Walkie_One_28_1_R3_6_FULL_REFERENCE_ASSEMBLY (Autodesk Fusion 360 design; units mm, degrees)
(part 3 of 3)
sketch "Sketch14" plane through (0, 0, -22) normal (0, 0, 1) x axis (1, 0, 0)
  line L1 (26.9755, 27.0732) -> (16.9755, 27.0732)
  line L2 (26.9755, 19.0732) -> (26.9755, 27.0732)
  line L3 (16.9755, 19.0732) -> (26.9755, 19.0732)
  line L4 (16.9755, 27.0732) -> (16.9755, 19.0732)
  line L5 (-26.4387, -62.9268) -> (-16.9755, -62.9268)
  curve K1 (-20, -67) -> (-25.5105, -65.6599)
  line L6 (20, -67) -> (-20, -67)
  curve K2 (25.5105, -65.6599) -> (20, -67)
  curve K3 (32, -55) -> (30.6599, -60.5105)
  line L7 (32, 1.6132) -> (32, -55)
  line L8 (22.6952, 1.6132) -> (32, 1.6132)
  line L9 (22.6952, 5.6132) -> (22.6952, 1.6132)
  line L10 (32, 5.6132) -> (22.6952, 5.6132)
  line L11 (32, 55) -> (32, 5.6132)
  curve K4 (30.6599, 60.5105) -> (32, 55)
  line L12 (-20, 67) -> (20, 67)
  curve K5 (-25.5105, 65.6599) -> (-20, 67)
  line L13 (-32, -55) -> (-32, 55)
  curve K6 (-30.6599, -60.5105) -> (-32, -55)
  line L14 (-26.9755, -54.9268) -> (-26.9755, -62.2512)
  line L15 (-16.9755, -54.9268) -> (-26.9755, -54.9268)
  line L16 (-16.9755, -62.9268) -> (-16.9755, -54.9268)
  curve K7 (20, 67) -> (25.5105, 65.6599)
  curve K8 (-32, 55) -> (-30.6599, 60.5105)
  arc A1 centre (-31, -66) radius 5.5 clockwise from (-26.4387, -62.9268) to (-25.5105, -65.6599)
  arc A2 centre (31, -66) radius 5.5 clockwise from (25.5105, -65.6599) to (30.6599, -60.5105)
  arc A3 centre (31, 66) radius 5.5 clockwise from (30.6599, 60.5105) to (25.5105, 65.6599)
  arc A4 centre (-31, 66) radius 5.5 clockwise from (-25.5105, 65.6599) to (-30.6599, 60.5105)
  arc A5 centre (-31, -66) radius 5.5 clockwise from (-30.6599, -60.5105) to (-26.9755, -62.2512)
  circle C1 centre (-26, 28) radius 3.5
  circle C2 centre (26, 56) radius 3.5
  circle C3 centre (-25, 56) radius 3.5
  dimension "d391" diameter C1 = 7
  dimension "d392" diameter C2 = 7
  dimension "d393" diameter C3 = 7
extrude "Extrude15" add sketch "Sketch14" profile of C1 C2 C3 along normal blind 5.35
fillet "Fillet4" radius 1
position "Position10"
copy_paste "CutPaste"
sketch "Sketch23" plane through (0, 0, 0) normal (0, 0, 1) x axis (1, 0, 0)
  line L1 (32, 55) -> (32, -55)
  line L2 (-20, 67) -> (20, 67)
  line L3 (-32, -55) -> (-32, 55)
  line L4 (20, -67) -> (-20, -67)
  line L5 (-12.5, 62.5) -> (12.5, 62.5)
  line L6 (-24, 24) -> (-24, 51)
  line L7 (12.5, 12.5) -> (-12.5, 12.5)
  line L8 (24, 51) -> (24, 24)
  line L9 (12.5, 60.5) -> (-12.5, 60.5)
  line L10 (-22, 51) -> (-22, 24)
  line L11 (22, 24) -> (22, 51)
  line L12 (-12.5, 14.5) -> (12.5, 14.5)
  arc A1 centre (20, -55) radius 12 clockwise from (32, -55) to (20, -67)
  arc A2 centre (20, 55) radius 12 clockwise from (20, 67) to (32, 55)
  arc A3 centre (-20, 55) radius 12 clockwise from (-32, 55) to (-20, 67)
  arc A4 centre (-20, -55) radius 12 clockwise from (-20, -67) to (-32, -55)
  circle C1 centre (-0.0141, 38) radius 18
  circle C2 centre (0, 0) radius 2.4048
  circle C3 centre (0.0002, -18.0006) radius 1.3009
  circle C4 centre (0, -47) radius 15.55
  arc A5 centre (-12.5, 51) radius 11.5 clockwise from (-24, 51) to (-12.5, 62.5)
  arc A6 centre (-12.5, 24) radius 11.5 clockwise from (-12.5, 12.5) to (-24, 24)
  arc A7 centre (12.5, 24) radius 11.5 clockwise from (24, 24) to (12.5, 12.5)
  arc A8 centre (12.5, 51) radius 11.5 clockwise from (12.5, 62.5) to (24, 51)
  arc A9 centre (-12.5, 51) radius 9.5 clockwise from (-22, 51) to (-12.5, 60.5)
  arc A10 centre (12.5, 51) radius 9.5 clockwise from (12.5, 60.5) to (22, 51)
  arc A11 centre (12.5, 24) radius 9.5 clockwise from (22, 24) to (12.5, 14.5)
  arc A12 centre (-12.5, 24) radius 9.5 clockwise from (-12.5, 14.5) to (-22, 24)
extrude "Extrude23" new body of existing geometry blind -1 from offset -0.6
sketch "Sketch24" plane through (0, 0, 0.95) normal (0, 0, 1) x axis (1, 0, 0)
  line L1 (-22, 51) -> (-22, 24)
  line L2 (12.5, 60.5) -> (-12.5, 60.5)
  line L3 (22, 24) -> (22, 51)
  line L4 (-12.5, 14.5) -> (12.5, 14.5)
  line L5 (-12.5, 62.5) -> (12.5, 62.5)
  line L6 (-24, 24) -> (-24, 51)
  line L7 (12.5, 12.5) -> (-12.5, 12.5)
  line L8 (24, 51) -> (24, 24)
  arc A1 centre (-12.5, 24) radius 9.5 clockwise from (-12.5, 14.5) to (-22, 24)
  arc A2 centre (-12.5, 51) radius 9.5 clockwise from (-22, 51) to (-12.5, 60.5)
  arc A3 centre (12.5, 51) radius 9.5 clockwise from (12.5, 60.5) to (22, 51)
  arc A4 centre (12.5, 24) radius 9.5 clockwise from (22, 24) to (12.5, 14.5)
  arc A5 centre (-12.5, 51) radius 11.5 clockwise from (-24, 51) to (-12.5, 62.5)
  arc A6 centre (-12.5, 24) radius 11.5 clockwise from (-12.5, 12.5) to (-24, 24)
  arc A7 centre (12.5, 24) radius 11.5 clockwise from (24, 24) to (12.5, 12.5)
  arc A8 centre (12.5, 51) radius 11.5 clockwise from (12.5, 62.5) to (24, 51)
sketch "Sketch14" plane through (0, 0, 0.95) normal (0, 0, 1) x axis (1, 0, 0)
  line L1 (-22, 51) -> (-22, 24)
  line L2 (12.5, 60.5) -> (-12.5, 60.5)
  line L3 (22, 24) -> (22, 51)
  line L4 (-12.5, 14.5) -> (12.5, 14.5)
  line L5 (-12.5, 62.5) -> (12.5, 62.5)
  line L6 (-24, 24) -> (-24, 51)
  line L7 (12.5, 12.5) -> (-12.5, 12.5)
  line L8 (24, 51) -> (24, 24)
  line L9 (12.5, 12.5) -> (-12.5, 12.5)
  line L10 (-24, 24) -> (-24, 51)
  line L11 (-12.5, 62.5) -> (12.5, 62.5)
  line L12 (24, 51) -> (24, 24)
  line L13 (-21, 24) -> (-21, 51)
  line L14 (12.5, 15.5) -> (-12.5, 15.5)
  line L15 (21, 51) -> (21, 24)
  line L16 (-12.5, 59.5) -> (12.5, 59.5)
  arc A1 centre (-12.5, 24) radius 9.5 clockwise from (-12.5, 14.5) to (-22, 24)
  arc A2 centre (-12.5, 51) radius 9.5 clockwise from (-22, 51) to (-12.5, 60.5)
  arc A3 centre (12.5, 51) radius 9.5 clockwise from (12.5, 60.5) to (22, 51)
  arc A4 centre (12.5, 24) radius 9.5 clockwise from (22, 24) to (12.5, 14.5)
  arc A5 centre (-12.5, 51) radius 11.5 clockwise from (-24, 51) to (-12.5, 62.5)
  arc A6 centre (-12.5, 24) radius 11.5 clockwise from (-12.5, 12.5) to (-24, 24)
  arc A7 centre (12.5, 24) radius 11.5 clockwise from (24, 24) to (12.5, 12.5)
  arc A8 centre (12.5, 51) radius 11.5 clockwise from (12.5, 62.5) to (24, 51)
  arc A9 centre (12.5, 24) radius 11.5 clockwise from (24, 24) to (12.5, 12.5)
  arc A10 centre (-12.5, 24) radius 11.5 clockwise from (-12.5, 12.5) to (-24, 24)
  arc A11 centre (-12.5, 51) radius 11.5 clockwise from (-24, 51) to (-12.5, 62.5)
  arc A12 centre (12.5, 51) radius 11.5 clockwise from (12.5, 62.5) to (24, 51)
  arc A13 centre (-12.5, 24) radius 8.5 clockwise from (-12.5, 15.5) to (-21, 24)
  arc A14 centre (12.5, 24) radius 8.5 clockwise from (21, 24) to (12.5, 15.5)
  arc A15 centre (12.5, 51) radius 8.5 clockwise from (12.5, 59.5) to (21, 51)
  arc A16 centre (-12.5, 51) radius 8.5 clockwise from (-21, 51) to (-12.5, 59.5)
  dimension "d402" = -3
place_component sketch "Sketch14"
extrude "Extrude1" new body sketch "Sketch14" along normal blind 2
delete_face "DeleteFace2"
delete_face "DeleteFace3"
sketch "Sketch15" plane through (-40, 0, 0) normal (-1, 0, 0) x axis (0, 0, 1)
  line L1 (-13.1579, -20.1868) -> (-12, -20.1868)
  line L2 (-16, -19.497) -> (-16, -55)
  line L3 (-12, -55) -> (-16, -55)
  line L4 (-12, -20.1868) -> (-12, -55)
  line L5 (-16.6, -42.5) -> (-15.5, -49.6)
  line L6 (-10.55, -37.05) -> (-21.55, -37.05)
  line L7 (-10.55, -55.05) -> (-10.55, -37.05)
  line L8 (-21.55, -55.05) -> (-10.55, -55.05)
  line L9 (-21.55, -37.05) -> (-21.55, -55.05)
  line L10 (-10.55, -55.05) -> (-21.55, -37.05)
  line L11 (-21.55, -55.05) -> (-10.55, -37.05)
  arc A1 centre (-13.1579, -13.9868) radius 6.2 clockwise from (-13.1579, -20.1868) to (-16, -19.497)
  point P14 (-16.05, -46.05)
  point P12 (-10.55, -55.05)
  point P13 (-21.55, -55.05)
  point P11 (-10.55, -37.05)
  horizontal L6
  perpendicular L6 L7
  parallel L6 L8
  parallel L7 L9
  coincident L10 P14
  coincident L11 P14
  midpoint L5 P14
  dimension "d415" distance P12 P13 = 11
  dimension "d416" distance P11 P12 = 18
extrude "Extrude16" cut sketch "Sketch15" profile of L2 L3 L4 L6 L7 L8 L9 against normal blind 6
fillet "Fillet7" radius 3.5
fillet "Fillet5" radius 3.5
sketch "Sketch16" plane through (0, 0, -12) normal (0, 0, 1) x axis (1, 0, 0)
  line L1 (-42.1, 77.1) -> (42.1, 77.1)
  line L2 (-42.1, -77.1) -> (-42.1, 77.1)
  line L3 (42.1, -77.1) -> (-42.1, -77.1)
  line L4 (42.1, 77.1) -> (42.1, -77.1)
  line L5 (-42.1, -77.1) -> (42.1, 77.1)
  line L6 (42.1, -77.1) -> (-42.1, 77.1)
  point P6 (0, 0)
  point P1 (0, 0)
  point P4 (-42.1, -77.1)
  point P5 (42.1, -77.1)
  point P3 (-42.1, 77.1)
  horizontal L1
  perpendicular L1 L2
  parallel L1 L3
  parallel L2 L4
  coincident L5 P6
  coincident L6 P6
  coincident P1 P6
  dimension "d425" distance P4 P5 = 84.2 (= "80.2 mm + 4 mm")
  dimension "d426" distance P3 P4 = 154.2 (= "150.2 mm + 4 mm")
extrude "Extrude1" new body sketch "Sketch16" profile of L1 L2 L3 L4 distance 14
fillet "Fillet1" radius 22
fillet "Fillet2" radius 12
extrude "Extrude2" cut of existing geometry blind -40
shell "Shell2" innerThickness 2
sketch "Sketch17" plane through (-41.9, 0, 0) normal (-1, 0, 0) x axis (0, 0, 1)
  line L1 (-12.1, 34) -> (-11.9, 34)
  line L2 (-18, -14.1) -> (-18, 28.1)
  line L3 (-11.9, -20) -> (-12.1, -20)
  line L4 (-6, 28.1) -> (-6, -14.1)
  line L5 (-18.5, -14.1) -> (-18.5, 28.1)
  line L6 (-11.9, -20.5) -> (-12.1, -20.5)
  line L7 (-5.5, 28.1) -> (-5.5, -14.1)
  line L8 (-12.1, 34.5) -> (-11.9, 34.5)
  arc A1 centre (-11.9, 28.1) radius 5.9 clockwise from (-11.9, 34) to (-6, 28.1)
  arc A2 centre (-12.1, 28.1) radius 5.9 clockwise from (-18, 28.1) to (-12.1, 34)
  arc A3 centre (-12.1, -14.1) radius 5.9 clockwise from (-12.1, -20) to (-18, -14.1)
  arc A4 centre (-11.9, -14.1) radius 5.9 clockwise from (-6, -14.1) to (-11.9, -20)
  arc A5 centre (-12.1, 28.1) radius 6.4 clockwise from (-18.5, 28.1) to (-12.1, 34.5)
  arc A6 centre (-12.1, -14.1) radius 6.4 clockwise from (-12.1, -20.5) to (-18.5, -14.1)
  arc A7 centre (-11.9, -14.1) radius 6.4 clockwise from (-5.5, -14.1) to (-11.9, -20.5)
  arc A8 centre (-11.9, 28.1) radius 6.4 clockwise from (-11.9, 34.5) to (-5.5, 28.1)
  dimension "d437" = 0.5
extrude "Extrude3" cut sketch "Sketch17" against normal blind 9 and along normal blind 3
sketch "Sketch18" plane through (41, 0, 0) normal (1, 0, 0) x axis (0, 0, -1)
  line L1 (6.5, -15) -> (6.5, -7)
  line L2 (12.1, -20.4) -> (11.9, -20.4)
  line L3 (17.5, -7) -> (17.5, -15)
  line L4 (11.9, -1.6) -> (12.1, -1.6)
  line L5 (11.95, -14) -> (12.05, -14)
  line L6 (11.5, -8.45) -> (11.5, -13.55)
  line L7 (12.05, -8) -> (11.95, -8)
  line L8 (12.5, -13.55) -> (12.5, -8.45)
  line L9 (12.1, -20.9) -> (11.9, -20.9)
  line L10 (18, -7) -> (18, -15)
  line L11 (11.9, -1.1) -> (12.1, -1.1)
  line L12 (6, -15) -> (6, -7)
  arc A1 centre (11.9, -15) radius 5.4 clockwise from (11.9, -20.4) to (6.5, -15)
  arc A2 centre (12.1, -15) radius 5.4 clockwise from (17.5, -15) to (12.1, -20.4)
  arc A3 centre (12.1, -7) radius 5.4 clockwise from (12.1, -1.6) to (17.5, -7)
  arc A4 centre (11.9, -7) radius 5.4 clockwise from (6.5, -7) to (11.9, -1.6)
  arc A5 centre (11.95, -13.55) radius 0.45 clockwise from (11.95, -14) to (11.5, -13.55)
  arc A6 centre (11.95, -8.45) radius 0.45 clockwise from (11.5, -8.45) to (11.95, -8)
  arc A7 centre (12.05, -8.45) radius 0.45 clockwise from (12.05, -8) to (12.5, -8.45)
  arc A8 centre (12.05, -13.55) radius 0.45 clockwise from (12.5, -13.55) to (12.05, -14)
  arc A9 centre (11.9, -15) radius 5.9 clockwise from (11.9, -20.9) to (6, -15)
  arc A10 centre (12.1, -15) radius 5.9 clockwise from (18, -15) to (12.1, -20.9)
  arc A11 centre (12.1, -7) radius 5.9 clockwise from (12.1, -1.1) to (18, -7)
  arc A12 centre (11.9, -7) radius 5.9 clockwise from (6, -7) to (11.9, -1.1)
  dimension "d442" = 0.5
extrude "Extrude4" cut sketch "Sketch18" along normal blind 4 and against normal blind 16
sketch "Sketch19" plane through (41, 0, 0) normal (1, 0, 0) x axis (0, 0, -1)
  line L1 (6.5, 14) -> (6.5, 22)
  line L2 (12.1, 8.6) -> (11.9, 8.6)
  line L3 (17.5, 22) -> (17.5, 14)
  line L4 (11.9, 27.4) -> (12.1, 27.4)
  line L5 (9.45, 17.5) -> (11.5, 17.5)
  line L6 (9, 18.05) -> (9, 17.95)
  line L7 (11.5, 18.5) -> (9.45, 18.5)
  line L8 (11.5, 20.55) -> (11.5, 18.5)
  line L9 (12.05, 21) -> (11.95, 21)
  line L10 (12.5, 18.5) -> (12.5, 20.55)
  line L11 (14.55, 18.5) -> (12.5, 18.5)
  line L12 (15, 17.95) -> (15, 18.05)
  line L13 (12.5, 17.5) -> (14.55, 17.5)
  line L14 (12.5, 15.45) -> (12.5, 17.5)
  line L15 (11.95, 15) -> (12.05, 15)
  line L16 (11.5, 17.5) -> (11.5, 15.45)
  line L17 (12.1, 8.1) -> (11.9, 8.1)
  line L18 (18, 22) -> (18, 14)
  line L19 (11.9, 27.9) -> (12.1, 27.9)
  line L20 (6, 14) -> (6, 22)
  arc A1 centre (11.9, 14) radius 5.4 clockwise from (11.9, 8.6) to (6.5, 14)
  arc A2 centre (12.1, 14) radius 5.4 clockwise from (17.5, 14) to (12.1, 8.6)
  arc A3 centre (12.1, 22) radius 5.4 clockwise from (12.1, 27.4) to (17.5, 22)
  arc A4 centre (11.9, 22) radius 5.4 clockwise from (6.5, 22) to (11.9, 27.4)
  arc A5 centre (9.45, 17.95) radius 0.45 clockwise from (9.45, 17.5) to (9, 17.95)
  arc A6 centre (9.45, 18.05) radius 0.45 clockwise from (9, 18.05) to (9.45, 18.5)
  arc A7 centre (11.95, 20.55) radius 0.45 clockwise from (11.5, 20.55) to (11.95, 21)
  arc A8 centre (12.05, 20.55) radius 0.45 clockwise from (12.05, 21) to (12.5, 20.55)
  arc A9 centre (14.55, 18.05) radius 0.45 clockwise from (14.55, 18.5) to (15, 18.05)
  arc A10 centre (14.55, 17.95) radius 0.45 clockwise from (15, 17.95) to (14.55, 17.5)
  arc A11 centre (12.05, 15.45) radius 0.45 clockwise from (12.5, 15.45) to (12.05, 15)
  arc A12 centre (11.95, 15.45) radius 0.45 clockwise from (11.95, 15) to (11.5, 15.45)
  arc A13 centre (11.9, 14) radius 5.9 clockwise from (11.9, 8.1) to (6, 14)
  arc A14 centre (12.1, 14) radius 5.9 clockwise from (18, 14) to (12.1, 8.1)
  arc A15 centre (12.1, 22) radius 5.9 clockwise from (12.1, 27.9) to (18, 22)
  arc A16 centre (11.9, 22) radius 5.9 clockwise from (6, 22) to (11.9, 27.9)
  dimension "d447" = 0.5
extrude "Extrude5" cut sketch "Sketch19" along normal blind 7 and against normal blind 8
sketch "Sketch20" plane through (-42.1, 0, 0) normal (-1, 0, 0) x axis (0, 0, 1)
  line L1 (-14, -55.1) -> (-14, -20.2115)
  line L2 (-10, -55.1) -> (-14, -55.1)
  line L3 (-10, -20.2115) -> (-10, -55.1)
  line L4 (-12.1, -20.5) -> (-11.9, -20.5)
  line L5 (-12, -37.05) -> (-16, -37.05)
  curve K1 (-21.55, -40.55) -> (-18.05, -37.05)
  line L6 (-16, -37.05) -> (-18.05, -37.05)
  line L7 (-21.55, -40.55) -> (-21.55, -51.55)
  curve K2 (-18.6395, -55) -> (-21.55, -51.55)
  line L8 (-18.05, -55.05) -> (-16, -55.05)
  curve K3 (-18.6395, -55) -> (-18.05, -55.05)
  line L9 (-16, -55.05) -> (-12, -55.05)
  curve K4 (-12, -55.05) -> (-11.9325, -55)
  line L10 (-10.55, -52.2132) -> (-10.55, -39.8868)
  arc A1 centre (-12.1, -14.1) radius 6.4 clockwise from (-12.1, -20.5) to (-14, -20.2115)
  arc A2 centre (-11.9, -14.1) radius 6.4 clockwise from (-10, -20.2115) to (-11.9, -20.5)
  arc A3 centre (-14.05, -39.8868) radius 3.5 clockwise from (-12, -37.05) to (-10.55, -39.8868)
  arc A4 centre (-14.05, -52.2132) radius 3.5 clockwise from (-10.55, -52.2132) to (-11.9325, -55)
extrude "Extrude6" cut sketch "Sketch20" profile of L1 A3 L5 K1 L6 L7 K2 L8 K3 L9 A4 K4 L10 against normal blind 9 and along normal blind 5
fillet "Fillet3" radius 1.55
sketch "Sketch21" plane through (0, 0, -3.5) normal (0, 0, -1) x axis (-1, 0, 0)
  circle C1 centre (0, 0) radius 2.7
  circle C2 centre (0, 0) radius 2.0248
  circle C3 centre (0, 0) radius 3.1828
  point P1 (0, 0)
  point P3 (0, 0)
  coincident P1 P3
  concentric C2 C3
extrude "Extrude1" cut sketch "Sketch21" along normal blind 7
offset_faces "OffsetFaces3" distance -0.1
offset_faces "OffsetFaces4" distance -0.1
offset_faces "OffsetFaces1" distance -1.444 (= "-1.244 mm - 0.2 mm")
delete_face "DeleteFace3"
offset_faces "OffsetFaces2" distance 0.95
offset_faces "OffsetFaces3" distance 1
offset_faces "OffsetFaces5" distance -1
extrude "Extrude9" cut of existing geometry blind -0.6
sketch "Sketch1" plane through (0, 0, 0.55) normal (0, 0, 1) x axis (1, 0, 0)
  line L1 (5, -47) -> (-3.3, -42)
  line L2 (-3.3, -52) -> (5, -47)
  line L3 (-3.3, -42) -> (-3.3, -52)
  circle C1 centre (0, -47) radius 13.35
  circle C2 centre (0, -47) radius 13.3
  concentric C1 C2
  dimension "d468" diameter C2 = 26.6 (= "13.3 mm * 2")
offset_faces "OffsetFaces6" distance -0.15
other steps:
extrude "Extrude2" cut sketch "Sketch12" against normal blind 6.5
extrude "Extrude14" cut sketch "Sketch6" against normal blind 6
extrude "Extrude25" cut sketch "Sketch15" profile of L2 L3 L4 L6 L7 L8 L9 against normal blind 6
create_component "CreateComponent3"
create_component "CreateComponent4"
create_component "CreateComponent6"
create_component "CreateComponent7"
create_component "CreateComponent9"
create_component "CreateComponent13"
create_component "CreateComponent14"
create_component "CreateComponent16"
create_component "CreateComponent17"
create_component "CreateComponent1"
create_component "CreateComponent2"
create_component "CreateComponent3"
create_component "CreateComponent4"
create_component "CreateComponent18"
create_component "CreateComponent1"
create_component "CreateComponent2"
create_component "CreateComponent3"
create_component "CreateComponent4"
create_component "CreateComponent5"
create_component "CreateComponent6"
create_component "CreateComponent7"
create_component "CreateComponent20"
create_component "CreateComponent21"
create_component "CreateComponent1"
create_component "CreateComponent1"
create_component "CreateComponent1"
create_component "CreateComponent2"
create_component "CreateComponent1"
create_component "CreateComponent3"
create_component "CreateComponent1"
create_component "CreateComponent4"
create_component "CreateComponent1"
create_component "CreateComponent5"
create_component "CreateComponent1"
create_component "CreateComponent6"
create_component "CreateComponent1"
create_component "CreateComponent7"
create_component "CreateComponent1"
create_component "CreateComponent8"
create_component "CreateComponent1"
create_component "CreateComponent9"
create_component "CreateComponent1"
create_component "CreateComponent10"
create_component "CreateComponent1"
create_component "CreateComponent11"
create_component "CreateComponent1"
create_component "CreateComponent1"
create_component "CreateComponent2"
create_component "CreateComponent12"
create_component "CreateComponent1"
create_component "CreateComponent13"
create_component "CreateComponent1"
create_component "CreateComponent14"
create_component "CreateComponent1"
create_component "CreateComponent1"
create_component "CreateComponent2"
create_component "CreateComponent15"
create_component "CreateComponent1"
create_component "CreateComponent16"
create_component "CreateComponent1"
create_component "CreateComponent1"
create_component "CreateComponent17"
create_component "CreateComponent1"
create_component "CreateComponent18"
create_component "CreateComponent1"
create_component "CreateComponent1"
create_component "CreateComponent2"
create_component "CreateComponent3"
create_component "CreateComponent4"
create_component "CreateComponent19"
create_component "CreateComponent1"
create_component "CreateComponent20"
create_component "CreateComponent1"
create_component "CreateComponent21"
create_component "CreateComponent1"
create_component "CreateComponent22"
create_component "CreateComponent22"
create_component "CreateComponent23"
create_component "CreateComponent24"
create_component "CreateComponent25" sketch "Sketch1"
create_component "CreateComponent26"
create_component "CreateComponent27"
create_component "CreateComponent28"
create_component "CreateComponent1"
create_component "CreateComponent1"
create_component "CreateComponent1"
create_component "CreateComponent1"
create_component "CreateComponent1"
create_component "CreateComponent2"
create_component "CreateComponent3"
create_component "CreateComponent4"
create_component "CreateComponent5"
create_component "CreateComponent6"
create_component "CreateComponent7"
create_component "CreateComponent8"
create_component "CreateComponent9"
create_component "CreateComponent10"
create_component "CreateComponent29"
create_component "CreateComponent30"
create_component "CreateComponent1"
create_component "CreateComponent2"
create_component "CreateComponent3"
create_component "CreateComponent4"
create_component "CreateComponent5"
create_component "CreateComponent6"
create_component "CreateComponent7"
create_component "CreateComponent8"
create_component "CreateComponent9"
create_component "CreateComponent10"
create_component "CreateComponent11"
create_component "CreateComponent12"
create_component "CreateComponent13"
create_component "CreateComponent14"
create_component "CreateComponent15"
create_component "CreateComponent16"
create_component "CreateComponent17"
create_component "CreateComponent18"
create_component "CreateComponent19"
create_component "CreateComponent20"
create_component "CreateComponent21"
create_component "CreateComponent22"
create_component "CreateComponent23"
create_component "CreateComponent24"
create_component "CreateComponent25"
create_component "CreateComponent26"
create_component "CreateComponent27"
create_component "CreateComponent28"
create_component "CreateComponent29"
create_component "CreateComponent30"
create_component "CreateComponent31"
create_component "CreateComponent32"
create_component "CreateComponent33"
create_component "CreateComponent31"
create_component "CreateComponent33"
create_component "CreateComponent34"
remove_body "RemoveBody1"
extrude "Extrude1" cut sketch "Sketch1" profile of A1 A2 L2 A3 A4 L4 L5 L6 A5 L7 A6 L8 L9 L10 L11 A7 L12 A8 L13 A9 L14 A10 L15 L17 along normal blind 6
extrude "Extrude1" cut sketch "Sketch1" profile of A1 A2 L2 A3 A4 L4 L5 L6 A5 L7 A6 L8 L9 L10 L11 A7 L12 A8 L13 A9 L14 A10 L15 L16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 along normal blind 9
create_component "CreateComponent35"
create_component "CreateComponent36"
remove_instance "RemoveInstance1"
create_component "CreateComponent37" sketch "Sketch14"
create_component "CreateComponent38"
named bodies: "C28_R2_Microphone_BOTTOM_PORT_Offset_Seal_REVIEW", "C28_R1_60_Black_Acoustic_Scrim", "Nominal U6 envelope - NOT SUPPLIER MODEL", "Adafruit board XY from Eagle - 0p8 thickness UNVERIFIED", "SPH0645 nominal envelope - bottom acoustic port - internal MEMS omitted", "C2 nominal passive envelope HEIGHT UNVERIFIED", "C4 nominal passive envelope HEIGHT UNVERIFIED", "R1 nominal passive envelope HEIGHT UNVERIFIED", "R2 nominal passive envelope HEIGHT UNVERIFIED", "C28_R3_REF_PTT_LIDUOLE_NOMINAL_6mm_NOT_OEM_1", "C28_R3_REF_PTT_LIDUOLE_NOMINAL_6mm_NOT_OEM_2", "C28_R3_REF_PTT_LIDUOLE_NOMINAL_6mm_NOT_OEM_3", "C28_R3_REF_PTT_LIDUOLE_NOMINAL_6mm_NOT_OEM_4", "C28_R3_REF_PTT_LIDUOLE_NOMINAL_6mm_NOT_OEM_5", "C28_R3_REF_PTT_LIDUOLE_NOMINAL_6mm_NOT_OEM_6", "C28_R3_REF_Volume_Up_LIDUOLE_NOMINAL_5mm_NOT_OEM_1", "C28_R3_REF_Volume_Up_LIDUOLE_NOMINAL_5mm_NOT_OEM_2", "C28_R3_REF_Volume_Up_LIDUOLE_NOMINAL_5mm_NOT_OEM_3", "C28_R3_REF_Volume_Up_LIDUOLE_NOMINAL_5mm_NOT_OEM_4", "C28_R3_REF_Volume_Up_LIDUOLE_NOMINAL_5mm_NOT_OEM_5", "C28_R3_REF_Volume_Up_LIDUOLE_NOMINAL_5mm_NOT_OEM_6", "C28_R3_REF_Volume_Down_LIDUOLE_NOMINAL_5mm_NOT_OEM_1", "C28_R3_REF_Volume_Down_LIDUOLE_NOMINAL_5mm_NOT_OEM_2", "C28_R3_REF_Volume_Down_LIDUOLE_NOMINAL_5mm_NOT_OEM_3", "C28_R3_REF_Volume_Down_LIDUOLE_NOMINAL_5mm_NOT_OEM_4", "C28_R3_REF_Volume_Down_LIDUOLE_NOMINAL_5mm_NOT_OEM_5", "C28_R3_REF_Volume_Down_LIDUOLE_NOMINAL_5mm_NOT_OEM_6", "C28_R3_REF_Front_LIDUOLE_NOMINAL_12x12x4p3_NOT_OEM_1", "C28_R3_REF_Front_LIDUOLE_NOMINAL_12x12x4p3_NOT_OEM_2", "C28_R3_REF_Front_LIDUOLE_NOMINAL_12x12x4p3_NOT_OEM_3", "C28_R3_REF_Front_LIDUOLE_NOMINAL_12x12x4p3_NOT_OEM_4", "C28_R3_REF_Front_LIDUOLE_NOMINAL_12x12x4p3_NOT_OEM_5", "C28_R3_REF_Front_LIDUOLE_NOMINAL_12x12x4p3_NOT_OEM_6", "C28_R3_4_F02_Flexible_Talk_Grip", "C28_R3_4_L01_Lens_Fit_Proxy", "C28_R3_4_L02_Light_Guide_Fit_Proxy", "C28_R3_6_P03_One_Piece_Play_Button", "C28_R3_6_P06_One_Piece_Volume_Up", "C28_R3_6_P07_One_Piece_Volume_Down", "C28_R3_4_L02_Light_Guide_Fit_Proxy (1)"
